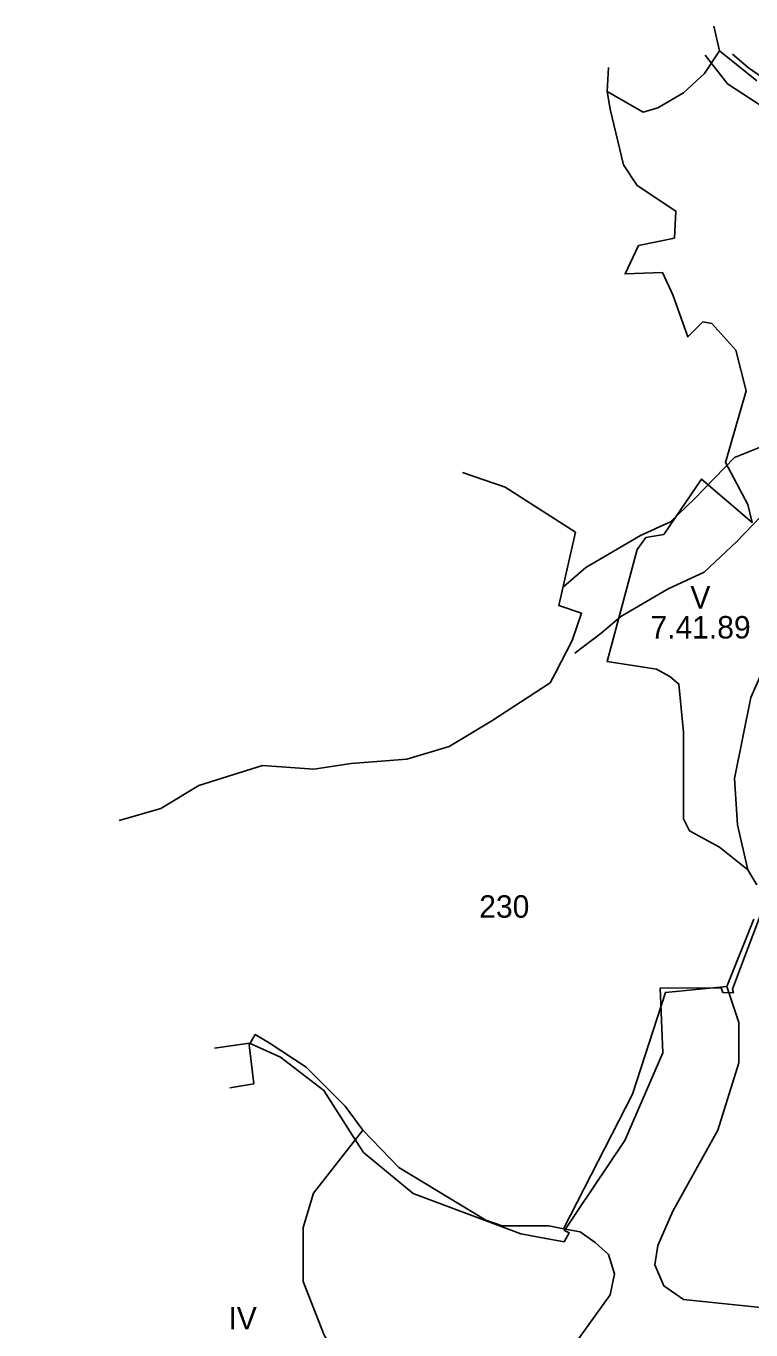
# Model space of a CAD drawing. Extents: x -694504 to -690518, y -983661 to -978958.
# Drawn here: x -694263 to -693779, y -981518 to -980647 of the extents above; entities that cross this region are included whole.
import ezdxf

# ---------------------------------------------------------------- set-up
doc = ezdxf.new("R2010")
doc.units = 0
for name, color, linetype in [('BPEJ', 7, 'Continuous'), ('kabelové a venkovní rozvody telefonu', 7, 'Continuous'), ('lokální biocentra', 7, 'Continuous'), ('nadregionální biokoridor', 7, 'Continuous'), ('ochranné pásmo silnic', 7, 'Continuous'), ('PŘÍRODNÍ PARK JEŠTĚD', 7, 'Continuous'), ('třídy přednosti v ochraně ZP', 7, 'Continuous')]:
    doc.layers.add(name, color=color, linetype=linetype)

msp = doc.modelspace()

# ---------------------------------------------------------------- linework, layer by layer
at = {"layer": 'BPEJ'}
for p, q in [((-693800.4, -980663.81), (-693804.15, -980647.21)), ((-693875.4, -980690.81), (-693874.4, -980674.81)), ((-694111.4, -981353.81), (-694127.3, -981356.57))]:
    msp.add_line(p, q, dxfattribs=at)
for points in [[(-693739.4, -981004.81), (-693779.4, -981095.81), (-693790.4, -981149.81), (-693788.4, -981180.81), (-693781.4, -981210.81), (-693800.4, -981195.81), (-693820.4, -981184.81), (-693824.4, -981176.81), (-693824.4, -981118.81), (-693827.4, -981086.81), (-693833.4, -981081.81), (-693842.4, -981076.81), (-693875.4, -981071.81), (-693855.4, -980996.81), (-693849.4, -980988.81), (-693837.4, -980986.81), (-693812.4, -980949.81), (-693778.4, -980978.81), (-693781.4, -980966.81), (-693796.4, -980938.81), (-693782.4, -980890.81), (-693789.4, -980863.81), (-693805.4, -980845.81), (-693811.4, -980844.81), (-693821.4, -980854.81), (-693831.4, -980826.81), (-693838.4, -980811.81), (-693863.4, -980812.81), (-693854.4, -980793.81), (-693830.4, -980788.81), (-693829.4, -980770.81), (-693855.4, -980753.81), (-693864.4, -980739.81), (-693873.4, -980702.81), (-693875.4, -980690.81), (-693851.4, -980704.81), (-693841.4, -980701.81), (-693824.4, -980691.81), (-693810.4, -980678.81), (-693800.4, -980663.81), (-693775.4, -980683.81)], [(-693775.4, -981220.81), (-693781.4, -981210.81), (-693788.4, -981180.81), (-693790.4, -981149.81), (-693779.4, -981095.81), (-693739.4, -981004.81)], [(-693768.4, -981503.81), (-693824.4, -981497.81), (-693837.4, -981488.81), (-693843.4, -981474.81), (-693841.4, -981461.81), (-693831.4, -981438.81), (-693801.4, -981384.81), (-693787.4, -981339.81), (-693787.4, -981312.81), (-693795.4, -981288.81), (-693777.4, -981243.81)], [(-693795.4, -981288.81), (-693836.4, -981292.81), (-693858.4, -981360.81), (-693904.4, -981450.81), (-693914.4, -981448.81), (-693945.4, -981448.81), (-693956.4, -981444.81), (-694014.4, -981409.81), (-694038.4, -981384.81), (-694050.4, -981368.81), (-694076.4, -981342.81), (-694100.4, -981326.81), (-694110.4, -981320.81), (-694114.4, -981327.81), (-694111.4, -981353.81)], [(-694038.4, -981384.81), (-694071.4, -981426.81), (-694078.4, -981449.81), (-694078.4, -981485.81), (-694064.4, -981521.81), (-694052.4, -981539.81), (-694038.4, -981551.81), (-694035.4, -981557.81), (-694040.4, -981575.81), (-694105.4, -981688.81), (-694136.4, -981737.81), (-694169.4, -981796.81), (-694205.4, -981793.81), (-694205.4, -981782.81), (-694216.4, -981756.81), (-694227.4, -981738.81), (-694245.4, -981739.81), (-694263.4, -981748.81)], [(-693904.4, -981450.81), (-693893.4, -981452.81), (-693883.4, -981459.81), (-693874.4, -981467.81), (-693870.4, -981480.81), (-693873.4, -981494.81), (-693914.4, -981551.81), (-693927.4, -981580.81), (-693933.4, -981615.81), (-693935.4, -981652.81), (-693955.4, -981688.81), (-694005.4, -981755.81), (-694018.4, -981786.81), (-694022.4, -981818.81), (-694019.4, -981868.81)]]:
    msp.add_lwpolyline(points, dxfattribs=at)
at = {"layer": 'kabelové a venkovní rozvody telefonu'}
msp.add_lwpolyline([(-693758.45, -980690.65), (-693781.03, -980675.1), (-693791.72, -980666.03)], dxfattribs=at)
at = {"layer": 'lokální biocentra'}
msp.add_lwpolyline([(-694201.14, -981177.82), (-694173.45, -981169.83), (-694148.01, -981154.55), (-694105.53, -981141.09), (-694071.32, -981143.6), (-694046.38, -981139.79), (-694009.15, -981136.91), (-693980.91, -981128.58), (-693952.42, -981111.36), (-693913.39, -981085.93), (-693909.94, -981079.29), (-693898.7, -981057.64), (-693892.42, -981039.42), (-693907.68, -981034.31), (-693896.53, -980985.41), (-693943.43, -980955.15), (-693972, -980945.46)], dxfattribs=at)
at = {"layer": 'nadregionální biokoridor'}
for points in [[(-693727.49, -980920.29), (-693769.15, -980926.87), (-693790.24, -980935.31), (-693816.91, -980963.08), (-693833.13, -980978.45), (-693853.04, -980987.5), (-693889.48, -981008.93), (-693904.33, -981021.66), (-693904.33, -981021.66), (-693904.33, -981021.66)], [(-693897.02, -981066.18), (-693897.02, -981066.18), (-693879.29, -981052.88), (-693866.14, -981041.61), (-693834.57, -981023.05), (-693810.48, -981012.1), (-693788.71, -980991.47), (-693767.37, -980969.24), (-693758.47, -980965.68), (-693728.89, -980961.01)]]:
    msp.add_lwpolyline(points, dxfattribs=at)
at = {"layer": 'ochranné pásmo silnic'}
msp.add_lwpolyline([(-693809.81, -980666.6), (-693795.02, -980685.9), (-693769.93, -980702.14)], dxfattribs=at)
at = {"layer": 'PŘÍRODNÍ PARK JEŠTĚD'}
msp.add_lwpolyline([(-694137.61, -981330.11), (-694114.14, -981326.7), (-694093.56, -981335.92), (-694064.53, -981358.22), (-694045.4, -981388.39), (-694038.02, -981399.69), (-694005, -981427.11), (-693932.88, -981453.94), (-693917.3, -981456.87), (-693904.1, -981459.36), (-693900.61, -981453.47), (-693903.87, -981451.9), (-693895.34, -981439.15), (-693863.54, -981391.61), (-693838.07, -981333.17), (-693839.83, -981289.84), (-693799.27, -981289.63), (-693798.14, -981292.81), (-693791.04, -981293.09), (-693791.58, -981290.66), (-693784.24, -981271.1), (-693768.03, -981227.94)], dxfattribs=at)

# ---------------------------------------------------------------- texts
at = {"layer": 'třídy přednosti v ochraně ZP'}
for s, p in [('V', (-693819.75, -981036.34)), ('7.41.89', (-693846.44, -981056.34)), ('230', (-693960.76, -981242.86)), ('IV', (-694128.26, -981517.95))]:
    msp.add_text(s, height=15, dxfattribs=at).set_placement(p)

doc.saveas('drawing.dxf')
